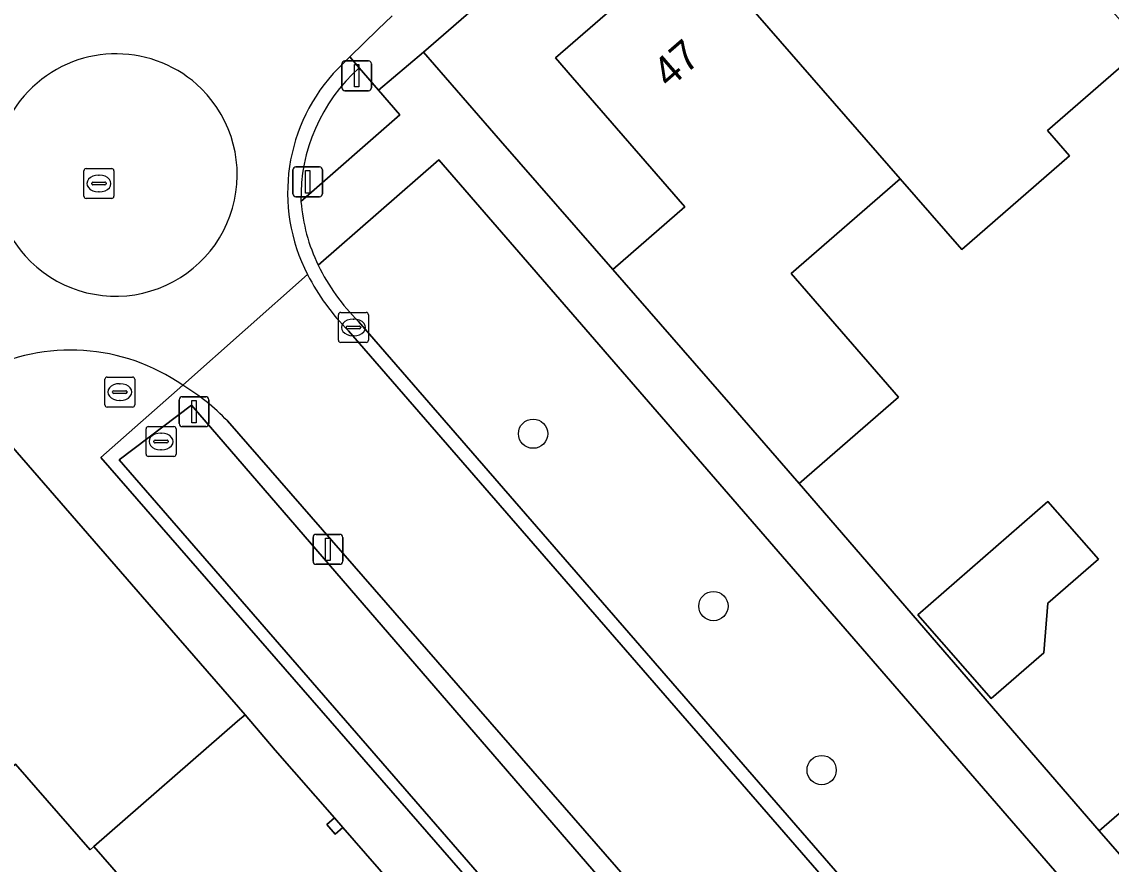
# Model space of a CAD drawing. Extents: x 155887 to 156869, y 383880 to 384678.
# Drawn here: x 156187.65 to 156224.02, y 384168.27 to 384196.41 of the extents above; entities that cross this region are included whole.
import ezdxf

# ---------------------------------------------------------------- set-up
doc = ezdxf.new("R2010")
doc.units = 0
for name, color, linetype in [('IMGEO_Afsluitpaal', 7, 'Continuous'), ('IMGEO_Berm_groen', 7, 'Continuous'), ('IMGEO_Boom', 7, 'Continuous'), ('IMGEO_Erf', 7, 'Continuous'), ('IMGEO_Greppel_droge_sloot', 7, 'Continuous'), ('IMGEO_Kolk', 7, 'Continuous'), ('IMGEO_Lichtmast', 7, 'Continuous'), ('IMGEO_Muur', 7, 'Continuous'), ('IMGEO_Pand', 7, 'Continuous'), ('IMGEO_Pand_nummerreeks', 7, 'Continuous'), ('IMGEO_Rijbaan_lokaal_gesloten', 7, 'Continuous'), ('IMGEO_Rijbaan_lokaal_open', 7, 'Continuous'), ('IMGEO_Rioolput', 7, 'Continuous'), ('IMGEO_Voetpad_open', 7, 'Continuous')]:
    doc.layers.add(name, color=color, linetype=linetype)

msp = doc.modelspace()

# ---------------------------------------------------------------- linework, layer by layer
at = {"layer": 'IMGEO_Afsluitpaal'}
for p, q in [((156198.337, 384194.208), (156198.337, 384195.008)), ((156198.337, 384195.008), (156198.337, 384194.208)), ((156198.437, 384195.108), (156199.227, 384195.108)), ((156199.227, 384195.108), (156198.437, 384195.108)), ((156199.327, 384195.008), (156199.327, 384194.208)), ((156199.327, 384194.208), (156199.327, 384195.008)), ((156199.227, 384194.108), (156198.437, 384194.108)), ((156198.437, 384194.108), (156199.227, 384194.108)), ((156196.802, 384191.564), (156197.592, 384191.564)), ((156197.592, 384191.564), (156196.802, 384191.564)), ((156196.702, 384190.664), (156196.702, 384191.464)), ((156196.702, 384191.464), (156196.702, 384190.664)), ((156197.692, 384191.464), (156197.692, 384190.664)), ((156197.692, 384190.664), (156197.692, 384191.464)), ((156197.592, 384190.564), (156196.802, 384190.564)), ((156196.802, 384190.564), (156197.592, 384190.564)), ((156193.006, 384183.887), (156193.796, 384183.887)), ((156193.796, 384183.887), (156193.006, 384183.887)), ((156192.906, 384182.987), (156192.906, 384183.787)), ((156192.906, 384183.787), (156192.906, 384182.987)), ((156193.896, 384183.787), (156193.896, 384182.987)), ((156193.896, 384182.987), (156193.896, 384183.787)), ((156193.796, 384182.887), (156193.006, 384182.887)), ((156193.006, 384182.887), (156193.796, 384182.887))]:
    msp.add_line(p, q, dxfattribs=at)
for points in [[(156198.757, 384194.983), (156198.907, 384194.983), (156198.907, 384194.233), (156198.757, 384194.233), (156198.757, 384194.983)], [(156197.122, 384191.439), (156197.272, 384191.439), (156197.272, 384190.689), (156197.122, 384190.689), (156197.122, 384191.439)], [(156193.326, 384183.762), (156193.476, 384183.762), (156193.476, 384183.012), (156193.326, 384183.012), (156193.326, 384183.762)]]:
    msp.add_lwpolyline(points, dxfattribs=at)
for centre, start, end in [((156198.437, 384195.008), 90, 180), ((156198.437, 384195.008), 90, 180), ((156199.227, 384195.008), 0, 90), ((156199.227, 384195.008), 360, 90), ((156198.437, 384194.208), 180, 270), ((156198.437, 384194.208), 180, 270), ((156199.227, 384194.208), 270, 0), ((156199.227, 384194.208), 270, 0), ((156196.802, 384191.464), 90, 180), ((156196.802, 384191.464), 90, 180), ((156197.592, 384191.464), 0, 90), ((156197.592, 384191.464), 360, 90), ((156196.802, 384190.664), 180, 270), ((156196.802, 384190.664), 180, 270), ((156197.592, 384190.664), 270, 0), ((156197.592, 384190.664), 270, 0), ((156193.006, 384183.787), 90, 180), ((156193.006, 384183.787), 90, 180), ((156193.796, 384183.787), 0, 90), ((156193.796, 384183.787), 360, 90), ((156193.006, 384182.987), 180, 270), ((156193.006, 384182.987), 180, 270), ((156193.796, 384182.987), 270, 0), ((156193.796, 384182.987), 270, 0)]:
    msp.add_arc(centre, 0.1, start, end, dxfattribs=at)
at = {"layer": 'IMGEO_Berm_groen'}
for points in [[(156200.274, 384193.303), (156199.564, 384194.123), (156198.918, 384194.869)], [(156196.972, 384190.404), (156200.274, 384193.303)], [(156201.574, 384191.802), (156197.546, 384188.282)], [(156198.894, 384186.401), (156225.459, 384155.791), (156226.35, 384155.089), (156230.362, 384158.557), (156201.574, 384191.802)], [(156193.025, 384184.269), (156190.289, 384181.852), (156219.036, 384148.836), (156221.841, 384151.236), (156221.169, 384152.485), (156194.519, 384183.079)]]:
    msp.add_lwpolyline(points, dxfattribs=at)
msp.add_lwpolyline([(156193.314, 384183.609), (156221.236, 384151.246), (156219.066, 384149.326), (156190.9, 384181.776)], close=True, dxfattribs=at)
for centre, radius, start, end in [((156202.764, 384190.536), 5.793, 131.5931, 181.3085), ((156203.783, 384191.328), 6.941, 206.0306, 225.2232), ((156189.255, 384178.003), 7.313, 43.9582, 58.9658)]:
    msp.add_arc(centre, radius, start, end, dxfattribs=at)
at = {"layer": 'IMGEO_Boom'}
for centre in [(156204.722, 384182.652), (156210.74, 384176.892), (156214.354, 384171.414)]:
    msp.add_circle(centre, 0.489, dxfattribs=at)
at = {"layer": 'IMGEO_Erf'}
for points in [[(156242.149, 384231.047), (156201.062, 384195.394), (156203.635, 384192.439), (156207.382, 384188.136), (156209.789, 384190.233), (156206.04, 384194.553), (156205.468, 384195.212), (156210.015, 384199.157), (156214.532, 384203.076), (156218.858, 384198.091), (156221.142, 384200.069), (156223.387, 384202.013), (156219.061, 384206.998), (156223.613, 384210.955), (156228.125, 384214.877), (156232.451, 384209.892), (156234.738, 384211.877), (156236.988, 384213.83), (156232.662, 384218.815), (156237.206, 384222.761), (156241.72, 384226.682), (156246.046, 384221.697), (156248.425, 384223.797), (156247.902, 384224.402)], [(156220.008, 384173.803), (156217.567, 384176.605), (156221.91, 384180.388), (156223.593, 384178.457), (156221.909, 384176.99), (156221.768, 384175.336)], [(156200.619, 384166.914), (156200.369, 384166.695), (156200.09, 384167.012), (156200.339, 384167.232), (156198.369, 384169.497), (156198.116, 384169.278), (156197.836, 384169.603), (156198.088, 384169.821), (156196.115, 384172.077), (156195.106, 384173.264), (156194.854, 384173.044), (156190.053, 384168.864), (156198.087, 384159.637), (156203.448, 384153.481), (156208.248, 384157.66), (156209.888, 384155.783), (156210.138, 384156.001), (156207.759, 384158.724), (156207.106, 384159.476), (156206.858, 384159.256), (156206.572, 384159.578), (156206.821, 384159.798)]]:
    msp.add_lwpolyline(points, close=True, dxfattribs=at)
msp.add_lwpolyline([(156225.107, 384195.576), (156221.889, 384192.783), (156222.629, 384191.931), (156219.037, 384188.801), (156216.977, 384191.166), (156213.335, 384188.004), (156214.645, 384186.494), (156216.92, 384183.872), (156213.609, 384180.988), (156223.615, 384169.382), (156226.945, 384172.275)], dxfattribs=at)
at = {"layer": 'IMGEO_Greppel_droge_sloot'}
msp.add_lwpolyline([(156219.066, 384149.326), (156221.236, 384151.246), (156193.314, 384183.609), (156190.9, 384181.776)], close=True, dxfattribs=at)
at = {"layer": 'IMGEO_Kolk'}
for p, q in [((156198.223, 384185.775), (156198.223, 384186.627)), ((156198.298, 384186.701), (156199.15, 384186.701)), ((156198.711, 384186.481), (156198.736, 384186.481)), ((156199.224, 384186.627), (156199.224, 384185.775)), ((156198.482, 384186.195), (156198.482, 384186.207)), ((156198.92, 384186.158), (156198.522, 384186.158)), ((156198.525, 384186.244), (156198.923, 384186.244)), ((156198.966, 384186.207), (156198.966, 384186.195)), ((156199.15, 384185.701), (156198.298, 384185.701)), ((156198.734, 384185.921), (156198.709, 384185.921)), ((156191.801, 384181.965), (156191.801, 384182.817)), ((156191.876, 384182.891), (156192.728, 384182.891)), ((156192.802, 384182.817), (156192.802, 384181.965)), ((156192.103, 384182.434), (156192.501, 384182.434)), ((156192.289, 384182.671), (156192.314, 384182.671)), ((156192.06, 384182.385), (156192.06, 384182.397)), ((156192.498, 384182.348), (156192.1, 384182.348)), ((156192.312, 384182.111), (156192.287, 384182.111)), ((156192.544, 384182.397), (156192.544, 384182.385)), ((156192.728, 384181.891), (156191.876, 384181.891))]:
    msp.add_line(p, q, dxfattribs=at)
for points in [[(156198.223, 384185.775), (156198.223, 384186.627)], [(156198.298, 384186.701), (156199.15, 384186.701)], [(156199.224, 384186.627), (156199.224, 384185.775)], [(156199.15, 384185.701), (156198.298, 384185.701)], [(156191.801, 384181.965), (156191.801, 384182.817)], [(156191.876, 384182.891), (156192.728, 384182.891)], [(156192.802, 384182.817), (156192.802, 384181.965)], [(156192.728, 384181.891), (156191.876, 384181.891)]]:
    msp.add_lwpolyline(points, dxfattribs=at)
for centre, radius, start, end in [((156198.3, 384186.625), 0.0765, 91.552, 178.448), ((156198.3, 384186.625), 0.0765, 91.552, 178.448), ((156199.148, 384186.625), 0.0765, 1.552, 88.448), ((156199.148, 384186.625), 0.0765, 1.552, 88.448), ((156198.522, 384186.204), 0.0403, 85.8775, 175.7526), ((156198.519, 384186.194), 0.0366, 178.938, 274.7102), ((156198.923, 384186.201), 0.043, 264.8664, 352.4533), ((156198.927, 384186.206), 0.0386, 1.7309, 96.639), ((156198.3, 384185.777), 0.0765, 181.552, 268.448), ((156198.3, 384185.777), 0.0765, 181.552, 268.448), ((156199.148, 384185.777), 0.0765, 271.552, 358.448), ((156199.148, 384185.777), 0.0765, 271.552, 358.448), ((156191.878, 384182.815), 0.0765, 91.552, 178.448), ((156191.878, 384182.815), 0.0765, 91.552, 178.448), ((156192.726, 384182.815), 0.0765, 1.552, 88.448), ((156192.726, 384182.815), 0.0765, 1.552, 88.448), ((156192.1, 384182.394), 0.0403, 85.8775, 175.7526), ((156192.505, 384182.396), 0.0386, 1.7309, 96.639), ((156192.097, 384182.384), 0.0366, 178.938, 274.7102), ((156192.501, 384182.391), 0.043, 264.8664, 352.4533), ((156191.878, 384181.967), 0.0765, 181.552, 268.448), ((156191.878, 384181.967), 0.0765, 181.552, 268.448), ((156192.726, 384181.967), 0.0765, 271.552, 358.448), ((156192.726, 384181.967), 0.0765, 271.552, 358.448)]:
    msp.add_arc(centre, radius, start, end, dxfattribs=at)
for centre, major_axis, ratio, start_param, end_param in [((156198.71, 384186.201), (-0.387, 0.002), 0.722429, 4.712389, 7.853982), ((156198.735, 384186.201), (-0.39, 0.002), 0.717154, 1.570796, 4.712389), ((156192.288, 384182.391), (-0.387, 0.002), 0.722429, 4.712389, 7.853982), ((156192.313, 384182.391), (-0.39, 0.002), 0.717154, 1.570796, 4.712389)]:
    msp.add_ellipse(centre, major_axis=major_axis, ratio=ratio, start_param=start_param, end_param=end_param, dxfattribs=at)
at = {"layer": 'IMGEO_Lichtmast'}
for p, q in [((156197.375, 384178.389), (156197.375, 384179.189)), ((156197.375, 384179.189), (156197.375, 384178.389)), ((156197.475, 384179.289), (156198.265, 384179.289)), ((156198.265, 384179.289), (156197.475, 384179.289)), ((156198.365, 384179.189), (156198.365, 384178.389)), ((156198.365, 384178.389), (156198.365, 384179.189)), ((156198.265, 384178.289), (156197.475, 384178.289)), ((156197.475, 384178.289), (156198.265, 384178.289))]:
    msp.add_line(p, q, dxfattribs=at)
msp.add_lwpolyline([(156197.795, 384179.164), (156197.945, 384179.164), (156197.945, 384178.414), (156197.795, 384178.414), (156197.795, 384179.164)], dxfattribs=at)
for centre, start, end in [((156197.475, 384179.189), 90, 180), ((156197.475, 384179.189), 90, 180), ((156198.265, 384179.189), 0, 90), ((156198.265, 384179.189), 360, 90), ((156197.475, 384178.389), 180, 270), ((156197.475, 384178.389), 180, 270), ((156198.265, 384178.389), 270, 0), ((156198.265, 384178.389), 270, 0)]:
    msp.add_arc(centre, 0.1, start, end, dxfattribs=at)
at = {"layer": 'IMGEO_Muur'}
msp.add_lwpolyline([(156213.609, 384180.988), (156223.615, 384169.382)], dxfattribs=at)
at = {"layer": 'IMGEO_Pand'}
for points in [[(156221.142, 384200.069), (156218.858, 384198.091), (156214.532, 384203.076), (156210.015, 384199.157), (156216.977, 384191.166), (156219.037, 384188.801), (156222.629, 384191.931), (156221.889, 384192.783), (156225.107, 384195.576)], [(156216.977, 384191.166), (156210.015, 384199.157), (156205.468, 384195.212), (156206.04, 384194.553), (156209.789, 384190.233), (156207.382, 384188.136), (156211.324, 384183.613), (156213.609, 384180.988), (156216.92, 384183.872), (156214.645, 384186.494), (156213.335, 384188.004)], [(156190.053, 384168.864), (156194.854, 384173.044), (156195.106, 384173.264), (156191.901, 384176.948), (156186.897, 384182.7), (156182.306, 384178.687), (156185.893, 384174.584), (156185.665, 384174.386), (156183.334, 384172.358), (156185.47, 384169.9), (156187.443, 384171.614), (156189.93, 384168.757)], [(156220.008, 384173.803), (156221.768, 384175.336), (156221.909, 384176.99), (156223.593, 384178.457), (156221.91, 384180.388), (156217.567, 384176.605)], [(156190.053, 384168.864), (156189.93, 384168.757), (156187.443, 384171.614), (156185.47, 384169.9), (156183.334, 384172.358), (156180.344, 384169.758), (156176.984, 384173.621), (156176.767, 384173.87), (156172.909, 384170.514), (156172.761, 384170.386), (156181.022, 384160.89), (156181.973, 384159.797), (156186.913, 384164.09), (156193.133, 384156.935), (156193.938, 384156.008), (156198.087, 384159.637)], [(156231.896, 384173.926), (156228.257, 384170.765), (156226.945, 384172.275), (156223.615, 384169.382), (156227.546, 384164.872), (156229.96, 384166.944), (156234.282, 384161.976), (156238.834, 384165.92)], [(156198.116, 384169.278), (156198.369, 384169.497), (156198.088, 384169.821), (156197.836, 384169.603)]]:
    msp.add_lwpolyline(points, close=True, dxfattribs=at)
at = {"layer": 'IMGEO_Rijbaan_lokaal_gesloten'}
for points in [[(156198.21, 384194.855), (156198.6, 384195.236), (156199.071, 384195.696), (156199.543, 384196.155), (156200.017, 384196.613)], [(156193.025, 384184.269), (156197.192, 384187.968)], [(156197.192, 384187.968), (156193.025, 384184.269)], [(156194.519, 384183.079), (156221.169, 384152.485), (156221.841, 384151.236), (156225.995, 384154.785), (156225.13, 384155.468), (156198.558, 384186.087)]]:
    msp.add_lwpolyline(points, dxfattribs=at)
for centre, radius, start, end in [((156190.802, 384191.285), 4.056, 45.4324, 221.549), ((156202.485, 384190.704), 5.959, 135.848, 207.3354), ((156190.787, 384191.301), 4.056, 221.8451, 45.1364), ((156203.692, 384191.252), 7.282, 206.8032, 225.1718), ((156189.287, 384178.916), 6.528, 55.073, 117.4477), ((156189.255, 384178.003), 7.313, 43.9582, 58.9658)]:
    msp.add_arc(centre, radius, start, end, dxfattribs=at)
at = {"layer": 'IMGEO_Rijbaan_lokaal_open'}
for points in [[(156198.918, 384194.869), (156198.6, 384195.236), (156198.21, 384194.855)], [(156198.558, 384186.087), (156225.13, 384155.468), (156225.995, 384154.785), (156226.35, 384155.089), (156225.459, 384155.791), (156198.894, 384186.401)]]:
    msp.add_lwpolyline(points, dxfattribs=at)
for centre, radius, start, end in [((156190.802, 384191.285), 4.056, 45.4324, 221.549), ((156202.485, 384190.704), 5.959, 135.848, 207.3354), ((156202.764, 384190.536), 5.793, 131.5931, 181.3085), ((156190.787, 384191.301), 4.056, 221.8451, 45.1364), ((156202.961, 384190.885), 6.008, 184.5956, 205.6769), ((156203.783, 384191.328), 6.941, 206.0306, 225.2232), ((156203.692, 384191.252), 7.282, 206.8032, 225.1718)]:
    msp.add_arc(centre, radius, start, end, dxfattribs=at)
at = {"layer": 'IMGEO_Rioolput'}
for p, q in [((156189.802, 384191.509), (156190.654, 384191.509)), ((156189.727, 384190.583), (156189.727, 384191.435)), ((156190.215, 384191.289), (156190.24, 384191.289)), ((156190.728, 384191.435), (156190.728, 384190.583)), ((156189.986, 384191.003), (156189.986, 384191.015)), ((156190.424, 384190.966), (156190.026, 384190.966)), ((156190.029, 384191.052), (156190.427, 384191.052)), ((156190.47, 384191.015), (156190.47, 384191.003)), ((156190.654, 384190.509), (156189.802, 384190.509)), ((156190.238, 384190.729), (156190.213, 384190.729)), ((156190.424, 384183.616), (156190.424, 384184.468)), ((156190.499, 384184.542), (156191.351, 384184.542)), ((156190.912, 384184.322), (156190.937, 384184.322)), ((156191.425, 384184.468), (156191.425, 384183.616)), ((156190.683, 384184.036), (156190.683, 384184.048)), ((156191.121, 384183.999), (156190.723, 384183.999)), ((156190.726, 384184.085), (156191.124, 384184.085)), ((156191.167, 384184.048), (156191.167, 384184.036)), ((156191.351, 384183.542), (156190.499, 384183.542)), ((156190.935, 384183.762), (156190.91, 384183.762))]:
    msp.add_line(p, q, dxfattribs=at)
for points in [[(156189.802, 384191.509), (156190.654, 384191.509)], [(156189.727, 384190.583), (156189.727, 384191.435)], [(156190.728, 384191.435), (156190.728, 384190.583)], [(156190.654, 384190.509), (156189.802, 384190.509)], [(156190.424, 384183.616), (156190.424, 384184.468)], [(156190.499, 384184.542), (156191.351, 384184.542)], [(156191.425, 384184.468), (156191.425, 384183.616)], [(156191.351, 384183.542), (156190.499, 384183.542)]]:
    msp.add_lwpolyline(points, dxfattribs=at)
for centre, radius, start, end in [((156189.804, 384191.433), 0.0765, 91.552, 178.448), ((156189.804, 384191.433), 0.0765, 91.552, 178.448), ((156190.652, 384191.433), 0.0765, 1.552, 88.448), ((156190.652, 384191.433), 0.0765, 1.552, 88.448), ((156190.026, 384191.012), 0.0403, 85.8775, 175.7526), ((156190.023, 384191.002), 0.0366, 178.938, 274.7102), ((156190.427, 384191.009), 0.043, 264.8664, 352.4533), ((156190.431, 384191.014), 0.0386, 1.7309, 96.639), ((156189.804, 384190.585), 0.0765, 181.552, 268.448), ((156189.804, 384190.585), 0.0765, 181.552, 268.448), ((156190.652, 384190.585), 0.0765, 271.552, 358.448), ((156190.652, 384190.585), 0.0765, 271.552, 358.448), ((156190.501, 384184.466), 0.0765, 91.552, 178.448), ((156190.501, 384184.466), 0.0765, 91.552, 178.448), ((156191.349, 384184.466), 0.0765, 1.552, 88.448), ((156191.349, 384184.466), 0.0765, 1.552, 88.448), ((156190.723, 384184.045), 0.0403, 85.8775, 175.7526), ((156190.72, 384184.035), 0.0366, 178.938, 274.7102), ((156191.124, 384184.042), 0.043, 264.8664, 352.4533), ((156191.128, 384184.047), 0.0386, 1.7309, 96.639), ((156190.501, 384183.618), 0.0765, 181.552, 268.448), ((156190.501, 384183.618), 0.0765, 181.552, 268.448), ((156191.349, 384183.618), 0.0765, 271.552, 358.448), ((156191.349, 384183.618), 0.0765, 271.552, 358.448)]:
    msp.add_arc(centre, radius, start, end, dxfattribs=at)
for centre, major_axis, ratio, start_param, end_param in [((156190.214, 384191.009), (-0.387, 0.002), 0.722429, 4.712389, 7.853982), ((156190.239, 384191.009), (-0.39, 0.002), 0.717154, 1.570796, 4.712389), ((156190.911, 384184.042), (-0.387, 0.002), 0.722429, 4.712389, 7.853982), ((156190.936, 384184.042), (-0.39, 0.002), 0.717154, 1.570796, 4.712389)]:
    msp.add_ellipse(centre, major_axis=major_axis, ratio=ratio, start_param=start_param, end_param=end_param, dxfattribs=at)
at = {"layer": 'IMGEO_Voetpad_open'}
for points in [[(156200.017, 384196.613), (156199.543, 384196.155), (156199.071, 384195.696), (156198.6, 384195.236), (156198.918, 384194.869), (156199.564, 384194.123), (156201.062, 384195.394), (156242.149, 384231.047), (156246.679, 384234.978), (156249.638, 384237.607), (156263.88, 384250)], [(156201.062, 384195.394), (156199.564, 384194.123), (156200.274, 384193.303), (156196.972, 384190.404)], [(156228.409, 384154.243), (156231.654, 384157.066), (156232.352, 384156.266), (156233.865, 384157.571), (156227.546, 384164.872), (156223.615, 384169.382), (156213.609, 384180.988), (156211.324, 384183.613), (156207.382, 384188.136), (156203.635, 384192.439), (156201.062, 384195.394)], [(156197.546, 384188.282), (156201.574, 384191.802), (156230.362, 384158.557), (156226.35, 384155.089)], [(156185.633, 384184.294), (156186.698, 384182.944), (156186.897, 384182.7), (156191.901, 384176.948), (156195.106, 384173.264), (156196.115, 384172.077), (156198.088, 384169.821), (156198.369, 384169.497), (156200.339, 384167.232), (156200.619, 384166.914), (156206.821, 384159.798), (156207.106, 384159.476), (156207.759, 384158.724), (156210.138, 384156.001), (156219.294, 384145.432), (156219.567, 384145.116), (156220.911, 384143.751)], [(156221.841, 384151.236), (156219.036, 384148.836), (156190.289, 384181.852), (156193.025, 384184.269)]]:
    msp.add_lwpolyline(points, dxfattribs=at)
for centre, radius, start, end in [((156202.961, 384190.885), 6.008, 184.5956, 205.6769), ((156189.287, 384178.916), 6.528, 55.073, 117.4477)]:
    msp.add_arc(centre, radius, start, end, dxfattribs=at)

# ---------------------------------------------------------------- texts
at = {"layer": 'IMGEO_Pand_nummerreeks'}
msp.add_text('47', height=1, rotation=40.9452, dxfattribs=at).set_placement((156209.259, 384194.16))

doc.saveas('drawing.dxf')
